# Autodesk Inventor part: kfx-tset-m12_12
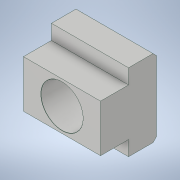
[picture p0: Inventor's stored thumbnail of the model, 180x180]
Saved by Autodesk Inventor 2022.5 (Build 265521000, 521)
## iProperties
Created: 2021-10
Part Number: kfx-tset-m12_12
Material: 一般
Document SubType Name: Modeling
Designer: ImaoCorp
Density: 1 g/cm^3
Appearance: 既定
Author: ImaoCorp
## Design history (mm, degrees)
feature "kfx-tset-m12_12"
node "ソリッド1"
